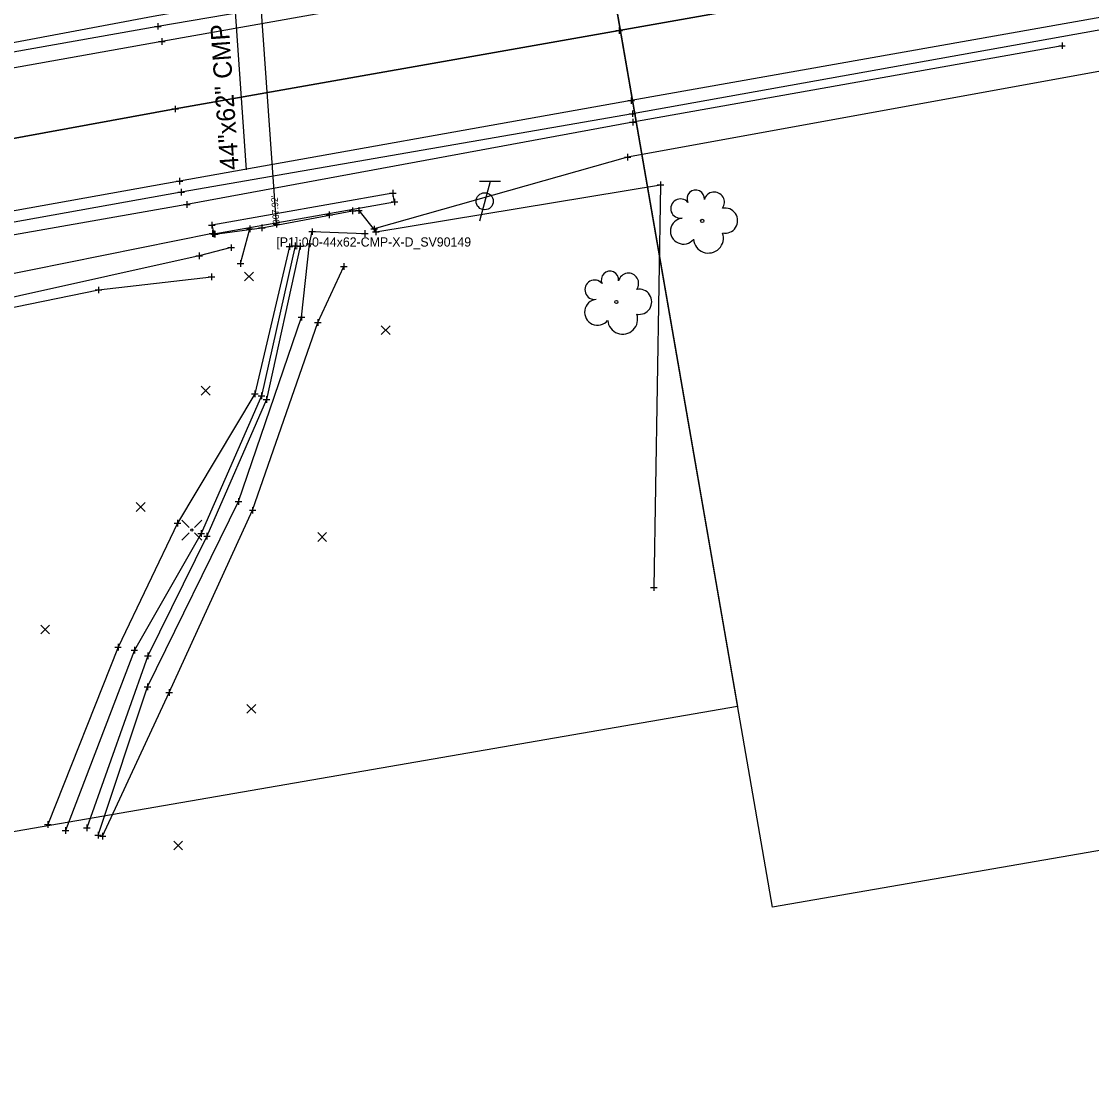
# Model space of a CAD drawing. Extents: x 1386013 to 1389776, y 604170 to 607009.
# Drawn here: x 1387613.6 to 1387776, y 604702.4 to 604864.4 of the extents above; entities that cross this region are included whole.
import ezdxf

# ---------------------------------------------------------------- set-up
doc = ezdxf.new("R2010")
doc.units = 0
for name, color, linetype in [('_CIVIL_CONSTRUCTION', 7, 'Continuous'), ('DR_X_Ditch', 7, 'Continuous'), ('DR_X_Headwall', 7, 'Continuous'), ('DR_X_Storm_Sewer', 7, 'Continuous'), ('DR_X_Text', 7, 'Continuous'), ('DV_X_Text', 7, 'Continuous'), ('PM_X_CL_Double_Solid', 7, 'Continuous'), ('PV_X_COP', 7, 'Continuous'), ('PV_X_EOP', 7, 'Continuous'), ('PV_X_Shoulder', 7, 'Continuous'), ('RD_X_Fence', 7, 'Continuous'), ('RD_X_GR_Lt', 7, 'Continuous'), ('RD_X_GR_Rt', 7, 'Continuous'), ('RW_P_Esmt_SH', 7, 'Continuous'), ('SC_Scratch1', 7, 'Continuous'), ('SH_Cut_Line', 7, 'Continuous'), ('SV_X_Break_Lines', 7, 'Continuous'), ('SV_X_Random_Point', 7, 'Continuous'), ('SV_X_Text', 7, 'Continuous'), ('SV_X_Toe_of_Slope', 7, 'Continuous'), ('SV_X_Top_of_Bank', 7, 'Continuous'), ('UT_X_Telecom_Cells', 7, 'Continuous')]:
    doc.layers.add(name, color=color, linetype=linetype)

msp = doc.modelspace()

# ---------------------------------------------------------------- linework, layer by layer
at = {"layer": '_CIVIL_CONSTRUCTION'}
for centre in [(1387716.96, 604834.12), (1387703.93, 604821.8)]:
    msp.add_circle(centre, 0.24, dxfattribs=at)
for centre, radius, start, end in [((1387715.97, 604837.49), 1.32, 354.0047, 205.9741), ((1387718.78, 604836.95), 1.55, 323.83, 165.0376), ((1387713.65, 604835.99), 1.47, 39.0625, 279.5412), ((1387720.42, 604834.16), 1.91, 259.1453, 101.4596), ((1387714.1, 604832.57), 1.97, 96.1722, 320.5737), ((1387717.9, 604831.52), 2.28, 184.9476, 19.4572), ((1387702.95, 604825.17), 1.32, 354.0047, 205.9741), ((1387705.76, 604824.63), 1.55, 323.83, 165.0376), ((1387700.62, 604823.67), 1.47, 39.0625, 279.5412), ((1387707.39, 604821.84), 1.91, 259.1453, 101.4596), ((1387701.08, 604820.25), 1.97, 96.1722, 320.5737), ((1387704.88, 604819.2), 2.28, 184.9476, 19.4572)]:
    msp.add_arc(centre, radius, start, end, dxfattribs=at)
at = {"layer": 'DR_X_Ditch'}
msp.add_lwpolyline([(1387655.96, 604830.3), (1387650.85, 604807), (1387641.8, 604786.24), (1387632.83, 604768.08), (1387623.58, 604741.96)], dxfattribs=at)
at = {"layer": 'DR_X_Headwall'}
msp.add_lwpolyline([(1387642.53, 604833.48), (1387642.82, 604832.15), (1387670.26, 604836.99), (1387670, 604838.34)], close=True, dxfattribs=at)
at = {"layer": 'DR_X_Storm_Sewer'}
msp.add_line((1387652.33, 604833.62), (1387649.48, 604874.12), dxfattribs=at)
at = {"layer": 'DR_X_Text'}
msp.add_line((1387645.83, 604869.29), (1387647.75, 604841.89), dxfattribs=at)
at = {"layer": 'DV_X_Text'}
for p, q in [((1387634.35, 604864.16), (1387634.35, 604863.16)), ((1387633.85, 604863.66), (1387634.85, 604863.66)), ((1387634.35, 604863.66), (1387634.35, 604863.66)), ((1387703.85, 604863.01), (1387704.85, 604863.01)), ((1387704.35, 604863.51), (1387704.35, 604862.51)), ((1387704.35, 604863.01), (1387704.35, 604863.01)), ((1387634.44, 604861.37), (1387635.44, 604861.37)), ((1387634.94, 604861.87), (1387634.94, 604860.87)), ((1387634.94, 604861.37), (1387634.94, 604861.37)), ((1387771.56, 604861.22), (1387771.56, 604860.22)), ((1387771.06, 604860.72), (1387772.06, 604860.72)), ((1387771.56, 604860.72), (1387771.56, 604860.72)), ((1387706.18, 604852.88), (1387706.18, 604851.88)), ((1387636.99, 604851.61), (1387636.99, 604850.61)), ((1387705.68, 604852.38), (1387706.68, 604852.38)), ((1387706.18, 604852.38), (1387706.18, 604852.38)), ((1387636.49, 604851.11), (1387637.49, 604851.11)), ((1387636.99, 604851.11), (1387636.99, 604851.11)), ((1387705.88, 604850.4), (1387706.88, 604850.4)), ((1387706.38, 604850.9), (1387706.38, 604849.9)), ((1387706.38, 604850.4), (1387706.38, 604850.4)), ((1387706.42, 604849.62), (1387706.42, 604848.62)), ((1387705.92, 604849.12), (1387706.92, 604849.12)), ((1387706.42, 604849.12), (1387706.42, 604849.12)), ((1387705.14, 604843.8), (1387706.14, 604843.8)), ((1387705.64, 604844.3), (1387705.64, 604843.3)), ((1387705.64, 604843.8), (1387705.64, 604843.8)), ((1387637.12, 604840.16), (1387638.12, 604840.16)), ((1387637.62, 604840.66), (1387637.62, 604839.66)), ((1387637.62, 604840.16), (1387637.62, 604840.16)), ((1387710.64, 604840.09), (1387710.64, 604839.09)), ((1387637.38, 604838.5), (1387638.38, 604838.5)), ((1387637.88, 604839), (1387637.88, 604838)), ((1387637.88, 604838.5), (1387637.88, 604838.5)), ((1387669.5, 604838.34), (1387670.5, 604838.34)), ((1387670, 604838.84), (1387670, 604837.84)), ((1387670, 604838.34), (1387670, 604838.34)), ((1387710.14, 604839.59), (1387711.14, 604839.59)), ((1387710.64, 604839.59), (1387710.64, 604839.59)), ((1387638.24, 604836.61), (1387639.24, 604836.61)), ((1387638.74, 604837.11), (1387638.74, 604836.11)), ((1387638.74, 604836.61), (1387638.74, 604836.61)), ((1387669.76, 604836.99), (1387670.76, 604836.99)), ((1387670.26, 604837.49), (1387670.26, 604836.49)), ((1387670.26, 604836.99), (1387670.26, 604836.99)), ((1387659.86, 604835.04), (1387660.86, 604835.04)), ((1387660.36, 604835.54), (1387660.36, 604834.54)), ((1387660.36, 604835.04), (1387660.36, 604835.04)), ((1387663.39, 604835.66), (1387664.39, 604835.66)), ((1387663.89, 604836.16), (1387663.89, 604835.16)), ((1387663.89, 604835.66), (1387663.89, 604835.66)), ((1387664.35, 604835.71), (1387665.35, 604835.71)), ((1387664.85, 604836.21), (1387664.85, 604835.21)), ((1387664.85, 604835.71), (1387664.85, 604835.71)), ((1387642.03, 604833.48), (1387643.03, 604833.48)), ((1387642.53, 604833.98), (1387642.53, 604832.98)), ((1387642.53, 604833.48), (1387642.53, 604833.48)), ((1387648.32, 604833.42), (1387648.32, 604832.42)), ((1387650.11, 604833.57), (1387650.11, 604832.57)), ((1387651.83, 604833.62), (1387652.83, 604833.62)), ((1387652.33, 604834.12), (1387652.33, 604833.12)), ((1387652.33, 604833.62), (1387652.33, 604833.62)), ((1387667.16, 604833.39), (1387667.16, 604832.39)), ((1387642.14, 604832.21), (1387643.14, 604832.21)), ((1387642.32, 604832.15), (1387643.32, 604832.15)), ((1387642.49, 604832.12), (1387643.49, 604832.12)), ((1387642.64, 604832.71), (1387642.64, 604831.71)), ((1387642.64, 604832.21), (1387642.64, 604832.21)), ((1387642.82, 604832.65), (1387642.82, 604831.65)), ((1387642.82, 604832.15), (1387642.82, 604832.15)), ((1387642.99, 604832.62), (1387642.99, 604831.62)), ((1387642.99, 604832.12), (1387642.99, 604832.12)), ((1387647.82, 604832.92), (1387648.82, 604832.92)), ((1387648.32, 604832.92), (1387648.32, 604832.92)), ((1387649.61, 604833.07), (1387650.61, 604833.07)), ((1387650.11, 604833.07), (1387650.11, 604833.07)), ((1387657.28, 604832.49), (1387658.28, 604832.49)), ((1387657.78, 604832.99), (1387657.78, 604831.99)), ((1387657.78, 604832.49), (1387657.78, 604832.49)), ((1387665.24, 604832.22), (1387666.24, 604832.22)), ((1387665.74, 604832.72), (1387665.74, 604831.72)), ((1387665.74, 604832.22), (1387665.74, 604832.22)), ((1387666.66, 604832.89), (1387667.66, 604832.89)), ((1387666.91, 604832.45), (1387667.91, 604832.45)), ((1387667.16, 604832.89), (1387667.16, 604832.89)), ((1387667.41, 604832.95), (1387667.41, 604831.95)), ((1387667.41, 604832.45), (1387667.41, 604832.45)), ((1387644.99, 604830.06), (1387645.99, 604830.06)), ((1387645.49, 604830.56), (1387645.49, 604829.56)), ((1387645.49, 604830.06), (1387645.49, 604830.06)), ((1387653.82, 604830.21), (1387654.82, 604830.21)), ((1387654.32, 604830.71), (1387654.32, 604829.71)), ((1387654.32, 604830.21), (1387654.32, 604830.21)), ((1387654.7, 604830.33), (1387655.7, 604830.33)), ((1387655.2, 604830.83), (1387655.2, 604829.83)), ((1387655.2, 604830.33), (1387655.2, 604830.33)), ((1387655.46, 604830.3), (1387656.46, 604830.3)), ((1387655.96, 604830.8), (1387655.96, 604829.8)), ((1387655.96, 604830.3), (1387655.96, 604830.3)), ((1387656.84, 604830.62), (1387657.84, 604830.62)), ((1387657.34, 604831.12), (1387657.34, 604830.12)), ((1387657.34, 604830.62), (1387657.34, 604830.62)), ((1387640.13, 604828.81), (1387641.13, 604828.81)), ((1387640.63, 604829.31), (1387640.63, 604828.31)), ((1387640.63, 604828.81), (1387640.63, 604828.81)), ((1387646.37, 604827.67), (1387647.37, 604827.67)), ((1387646.87, 604828.17), (1387646.87, 604827.17)), ((1387646.87, 604827.67), (1387646.87, 604827.67)), ((1387662.05, 604827.21), (1387663.05, 604827.21)), ((1387662.55, 604827.71), (1387662.55, 604826.71)), ((1387662.55, 604827.21), (1387662.55, 604827.21)), ((1387641.98, 604825.61), (1387642.98, 604825.61)), ((1387642.48, 604826.11), (1387642.48, 604825.11)), ((1387642.48, 604825.61), (1387642.48, 604825.61)), ((1387624.82, 604823.63), (1387625.82, 604823.63)), ((1387625.32, 604824.13), (1387625.32, 604823.13)), ((1387625.32, 604823.63), (1387625.32, 604823.63)), ((1387655.65, 604819.5), (1387656.65, 604819.5)), ((1387656.15, 604820), (1387656.15, 604819)), ((1387656.15, 604819.5), (1387656.15, 604819.5)), ((1387658.14, 604818.71), (1387659.14, 604818.71)), ((1387658.64, 604819.21), (1387658.64, 604818.21)), ((1387658.64, 604818.71), (1387658.64, 604818.71)), ((1387648.56, 604807.85), (1387649.56, 604807.85)), ((1387649.06, 604808.35), (1387649.06, 604807.35)), ((1387649.06, 604807.85), (1387649.06, 604807.85)), ((1387649.56, 604807.55), (1387650.56, 604807.55)), ((1387650.06, 604808.05), (1387650.06, 604807.05)), ((1387650.06, 604807.55), (1387650.06, 604807.55)), ((1387650.85, 604807.5), (1387650.85, 604806.5)), ((1387650.35, 604807), (1387651.35, 604807)), ((1387650.85, 604807), (1387650.85, 604807)), ((1387646.09, 604791.5), (1387647.09, 604791.5)), ((1387646.59, 604792), (1387646.59, 604791)), ((1387646.59, 604791.5), (1387646.59, 604791.5)), ((1387648.23, 604790.18), (1387649.23, 604790.18)), ((1387648.73, 604790.68), (1387648.73, 604789.68)), ((1387648.73, 604790.18), (1387648.73, 604790.18)), ((1387636.84, 604788.21), (1387637.84, 604788.21)), ((1387637.34, 604788.71), (1387637.34, 604787.71)), ((1387637.34, 604788.21), (1387637.34, 604788.21)), ((1387640.4, 604786.64), (1387641.4, 604786.64)), ((1387640.9, 604787.14), (1387640.9, 604786.14)), ((1387640.9, 604786.64), (1387640.9, 604786.64)), ((1387641.3, 604786.24), (1387642.3, 604786.24)), ((1387641.8, 604786.74), (1387641.8, 604785.74)), ((1387641.8, 604786.24), (1387641.8, 604786.24)), ((1387709.13, 604778.45), (1387710.13, 604778.45)), ((1387709.63, 604778.95), (1387709.63, 604777.95)), ((1387709.63, 604778.45), (1387709.63, 604778.45)), ((1387627.8, 604769.39), (1387628.8, 604769.39)), ((1387628.3, 604769.89), (1387628.3, 604768.89)), ((1387628.3, 604769.39), (1387628.3, 604769.39)), ((1387630.28, 604768.93), (1387631.28, 604768.93)), ((1387630.78, 604769.43), (1387630.78, 604768.43)), ((1387630.78, 604768.93), (1387630.78, 604768.93)), ((1387632.83, 604768.58), (1387632.83, 604767.58)), ((1387632.33, 604768.08), (1387633.33, 604768.08)), ((1387632.83, 604768.08), (1387632.83, 604768.08)), ((1387632.78, 604763.88), (1387632.78, 604762.88)), ((1387632.28, 604763.38), (1387633.28, 604763.38)), ((1387632.78, 604763.38), (1387632.78, 604763.38)), ((1387635.55, 604762.51), (1387636.55, 604762.51)), ((1387636.05, 604763.01), (1387636.05, 604762.01)), ((1387636.05, 604762.51), (1387636.05, 604762.51)), ((1387617.16, 604742.49), (1387618.16, 604742.49)), ((1387617.66, 604742.99), (1387617.66, 604741.99)), ((1387617.66, 604742.49), (1387617.66, 604742.49)), ((1387623.58, 604742.46), (1387623.58, 604741.46)), ((1387619.85, 604741.55), (1387620.85, 604741.55)), ((1387620.35, 604742.05), (1387620.35, 604741.05)), ((1387620.35, 604741.55), (1387620.35, 604741.55)), ((1387623.08, 604741.96), (1387624.08, 604741.96)), ((1387623.58, 604741.96), (1387623.58, 604741.96)), ((1387624.78, 604740.86), (1387625.78, 604740.86)), ((1387625.28, 604741.36), (1387625.28, 604740.36)), ((1387625.28, 604740.86), (1387625.28, 604740.86)), ((1387625.97, 604741.2), (1387625.97, 604740.2)), ((1387625.47, 604740.7), (1387626.47, 604740.7)), ((1387625.97, 604740.7), (1387625.97, 604740.7))]:
    msp.add_line(p, q, dxfattribs=at)
at = {"layer": 'PM_X_CL_Double_Solid'}
msp.add_lwpolyline([(1386941.92, 604730.57), (1387000.37, 604739.9), (1387059.38, 604750.41), (1387127.32, 604761.93), (1387175.52, 604769.9), (1387233.31, 604779.13), (1387291.85, 604789.88), (1387343.04, 604798.39), (1387403.9, 604809.05), (1387458.49, 604818.93), (1387516.12, 604829.58), (1387574.82, 604839.73), (1387636.99, 604851.11), (1387704.35, 604863.01), (1387787.5, 604877.74), (1387859.73, 604890.76), (1387934.47, 604903.86), (1387998.85, 604914.97), (1388072.27, 604927.44)], dxfattribs=at)
at = {"layer": 'PV_X_COP'}
msp.add_lwpolyline([(1388072.27, 604927.44), (1387998.85, 604914.97), (1387934.47, 604903.86), (1387859.73, 604890.76), (1387787.5, 604877.74), (1387704.35, 604863.01), (1387636.99, 604851.11), (1387574.82, 604839.73), (1387516.12, 604829.58), (1387458.49, 604818.93), (1387403.9, 604809.05), (1387343.04, 604798.39), (1387291.85, 604789.88), (1387233.31, 604779.13), (1387175.52, 604769.9), (1387127.32, 604761.93), (1387059.38, 604750.41), (1387000.37, 604739.9), (1386941.92, 604730.57)], dxfattribs=at)
at = {"layer": 'PV_X_EOP'}
for points in [[(1388070.9, 604937.92), (1387997.67, 604925.46), (1387932.45, 604914.15), (1387857.85, 604900.92), (1387785.1, 604888.09), (1387704.04, 604873.65), (1387634.94, 604861.37), (1387573.23, 604850.33), (1387514.48, 604840.1), (1387457.17, 604829.65), (1387402.44, 604819.9), (1387341.38, 604808.9), (1387290.36, 604800.04), (1387231.98, 604789.91), (1387174.35, 604780.15), (1387125.76, 604771.91), (1387057.82, 604760.3), (1386999.09, 604750.97), (1386941.41, 604741.04)], [(1388073.48, 604916.74), (1388000.2, 604904.18), (1387936.61, 604893.17), (1387861, 604879.89), (1387788.15, 604866.91), (1387706.18, 604852.38), (1387637.62, 604840.16), (1387577.04, 604829.26), (1387518.08, 604818.58), (1387459.96, 604808.24), (1387405.36, 604798.5), (1387345.11, 604787.75), (1387291.8, 604778.43), (1387234.86, 604768.47), (1387177.43, 604758.7), (1387129.4, 604750.56), (1387061.72, 604739.2), (1387002.9, 604729.17), (1386943.42, 604719.4)]]:
    msp.add_lwpolyline(points, dxfattribs=at)
at = {"layer": 'PV_X_Shoulder'}
for points in [[(1388070.88, 604939.75), (1387997.08, 604927.24), (1387932.1, 604916.23), (1387857.34, 604902.99), (1387785.16, 604890.04), (1387703.39, 604875.43), (1387634.35, 604863.66), (1387572.42, 604852.64), (1387514.1, 604842.11), (1387456.78, 604832.26), (1387401.91, 604822.43), (1387340.63, 604811.34), (1387290.11, 604802.67), (1387231.45, 604791.93), (1387174.18, 604782.71), (1387125.33, 604774.1), (1387057.54, 604762.26), (1386998.59, 604752.7), (1386940.97, 604743.32)], [(1388073.66, 604915.38), (1388000.63, 604902.69), (1387936.79, 604891.84), (1387860.98, 604878.42), (1387788.19, 604865.06), (1387706.38, 604850.4), (1387637.88, 604838.5), (1387577.02, 604827.53), (1387518.12, 604817.16), (1387460.26, 604806.85), (1387405.51, 604796.97), (1387345.32, 604786.5), (1387292.14, 604776.93), (1387235.04, 604767.03), (1387177.5, 604757.13), (1387129.28, 604748.59), (1387117.65, 604744.89), (1387099.29, 604741.91), (1387094.7, 604743.05), (1387062.03, 604737.87), (1387002.75, 604727.47), (1386990.61, 604725.25), (1386985.4, 604722.84), (1386965.11, 604719.46)]]:
    msp.add_lwpolyline(points, dxfattribs=at)
at = {"layer": 'RD_X_Fence'}
for points in [[(1387664.85, 604835.71), (1387667.41, 604832.45), (1387710.64, 604839.59), (1387709.63, 604778.45)], [(1387646.87, 604827.67), (1387648.32, 604832.92)]]:
    msp.add_lwpolyline(points, dxfattribs=at)
at = {"layer": 'RD_X_GR_Lt'}
msp.add_lwpolyline([(1387771.56, 604860.72), (1387706.42, 604849.12), (1387638.74, 604836.61), (1387577.5, 604825.85), (1387497.27, 604812.51)], dxfattribs=at)
at = {"layer": 'RD_X_GR_Rt'}
msp.add_lwpolyline([(1387774.57, 604889.52), (1387703.04, 604877.37), (1387633.65, 604865.16), (1387573.86, 604853.92)], dxfattribs=at)
at = {"layer": 'RW_P_Esmt_SH'}
for p, q in [((1387637.99, 604788.69), (1387639.08, 604787.59)), ((1387639.91, 604787.59), (1387641.01, 604788.69)), ((1387637.99, 604785.67), (1387639.08, 604786.76)), ((1387639.91, 604786.76), (1387641.01, 604785.67))]:
    msp.add_line(p, q, dxfattribs=at)
msp.add_circle((1387639.5, 604787.18), 0.17, dxfattribs=at)
at = {"layer": 'SH_Cut_Line'}
for points in [[(1387727.6, 604729.92), (1387690.05, 604946.7), (1388025.06, 605004.73), (1388062.61, 604787.96)], [(1387387.31, 604702.37), (1387349.76, 604919.15), (1387684.77, 604977.18), (1387722.32, 604760.41)]]:
    msp.add_lwpolyline(points, close=True, dxfattribs=at)
at = {"layer": 'SV_X_Break_Lines'}
msp.add_lwpolyline([(1387642.99, 604832.12), (1387650.11, 604833.07), (1387663.89, 604835.66)], dxfattribs=at)
at = {"layer": 'SV_X_Random_Point'}
for p, q in [((1387647.52, 604825), (1387648.85, 604826.34)), ((1387647.52, 604826.34), (1387648.85, 604825)), ((1387668.25, 604816.85), (1387669.58, 604818.18)), ((1387668.25, 604818.18), (1387669.58, 604816.85)), ((1387640.93, 604807.67), (1387642.26, 604809.01)), ((1387640.93, 604809.01), (1387642.26, 604807.67)), ((1387631.07, 604790), (1387632.41, 604791.34)), ((1387631.07, 604791.34), (1387632.41, 604790)), ((1387658.61, 604785.46), (1387659.95, 604786.8)), ((1387658.61, 604786.8), (1387659.95, 604785.46)), ((1387616.58, 604771.42), (1387617.92, 604772.76)), ((1387616.58, 604772.76), (1387617.92, 604771.42)), ((1387647.86, 604759.36), (1387649.19, 604760.7)), ((1387647.86, 604760.7), (1387649.19, 604759.36)), ((1387636.77, 604738.63), (1387638.11, 604739.96)), ((1387636.77, 604739.96), (1387638.11, 604738.63))]:
    msp.add_line(p, q, dxfattribs=at)
at = {"layer": 'SV_X_Toe_of_Slope'}
for points in [[(1387959.03, 604890.44), (1387937.87, 604886.76), (1387862.3, 604872.74), (1387789.95, 604859.14), (1387705.64, 604843.8), (1387667.16, 604832.89)], [(1387642.64, 604832.21), (1387598.48, 604823.3), (1387558.95, 604817.37), (1387510.99, 604808.94), (1387471.62, 604802.75), (1387417.67, 604793.63), (1387365.33, 604784.07), (1387322.85, 604775.64), (1387270.33, 604764.8), (1387223.53, 604756.91), (1387181.6, 604750.67), (1387155.52, 604744), (1387129.15, 604740.81), (1387125.03, 604741.78), (1387120.43, 604741.02)], [(1387625.28, 604740.86), (1387632.78, 604763.38), (1387646.59, 604791.5), (1387656.15, 604819.5), (1387657.34, 604830.62), (1387657.78, 604832.49), (1387665.74, 604832.22)], [(1387645.49, 604830.06), (1387640.63, 604828.81), (1387599.43, 604819.65), (1387560.44, 604813.11), (1387511.64, 604804.79), (1387472.9, 604799.01), (1387418.9, 604788.91), (1387366.41, 604779.89), (1387324.47, 604770.63), (1387271.89, 604759.84), (1387225.55, 604751.97), (1387182.66, 604746.29), (1387156.28, 604739.69), (1387120.85, 604736.53)], [(1387655.2, 604830.33), (1387650.06, 604807.55), (1387640.9, 604786.64), (1387630.78, 604768.93), (1387620.35, 604741.55)]]:
    msp.add_lwpolyline(points, dxfattribs=at)
at = {"layer": 'SV_X_Top_of_Bank'}
for points in [[(1387654.32, 604830.21), (1387649.06, 604807.85), (1387637.34, 604788.21), (1387628.3, 604769.39), (1387617.66, 604742.49)], [(1387625.97, 604740.7), (1387636.05, 604762.51), (1387648.73, 604790.18), (1387658.64, 604818.71), (1387662.55, 604827.21)], [(1387120.44, 604732.56), (1387162.47, 604738.46), (1387215.74, 604745.53), (1387273.8, 604754.33), (1387315.9, 604762.49), (1387378.29, 604774.45), (1387445.09, 604787.58), (1387492, 604798.41), (1387538.69, 604807.91), (1387587.5, 604815.89), (1387625.32, 604823.63), (1387642.48, 604825.61)]]:
    msp.add_lwpolyline(points, dxfattribs=at)
at = {"layer": 'UT_X_Telecom_Cells'}
for p, q in [((1387684.76, 604840.1), (1387683.15, 604834.1)), ((1387686.36, 604840.1), (1387683.16, 604840.1))]:
    msp.add_line(p, q, dxfattribs=at)
msp.add_circle((1387683.95, 604837.1), 1.3, dxfattribs=at)

# ---------------------------------------------------------------- texts
at = {"layer": 'DR_X_Text'}
msp.add_text('44"x62" CMP', height=2.8, rotation=94.0202, dxfattribs=at).set_placement((1387646.64, 604841.93))
at = {"layer": 'SC_Scratch1'}
msp.add_text("907.92'", height=1, rotation=94.0202, dxfattribs=at).set_placement((1387652.82, 604833.66))
at = {"layer": 'SV_X_Text'}
msp.add_text('[P1]:0.0-44x62-CMP-X-D_SV90149', height=1.4, dxfattribs=at).set_placement((1387652.33, 604830.22))

doc.saveas('drawing.dxf')
